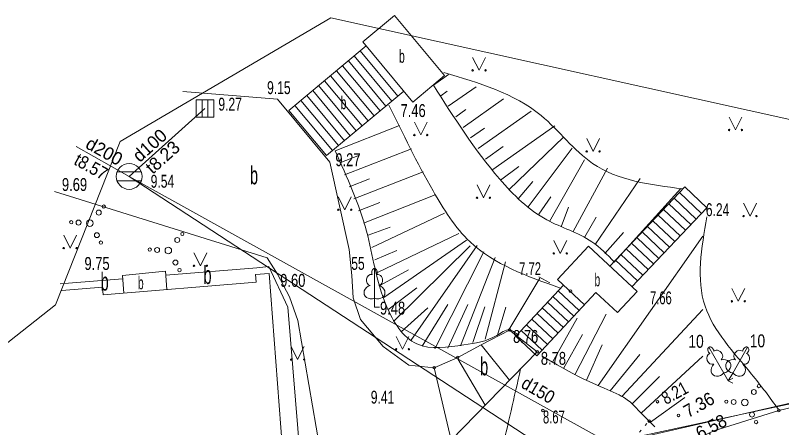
# Model space of a CAD drawing. Extents: x -1325 to -1182, y 698 to 905.
# Drawn here: x -1262.25 to -1232.55, y 829.61 to 845.58 of the extents above; entities that cross this region are included whole.
import ezdxf
from ezdxf.enums import TextEntityAlignment as Align

# ---------------------------------------------------------------- set-up
doc = ezdxf.new("R2010")
doc.units = 0
doc.header["$LTSCALE"] = 0.2
doc.linetypes.add('DOTTED', pattern=[1.5, 0.3, -1.2])
for name, color, linetype, lineweight in [('1', 7, 'Continuous', 13), ('20', 7, 'Continuous', 13), ('28', 7, 'Continuous', 13), ('3', 7, 'Continuous', 13), ('30', 7, 'Continuous', 13), ('5', 7, 'Continuous', 13), ('55', 7, 'Continuous', 13), ('56', 7, 'Continuous', 13), ('57', 7, 'DOTTED', 13), ('59', 7, 'Continuous', 13), ('6', 7, 'Continuous', 13), ('61', 7, 'Continuous', 13), ('62', 7, 'Continuous', 13), ('63', 7, 'Continuous', 13)]:
    doc.layers.add(name, color=color, linetype=linetype, lineweight=lineweight)
for name, color, linetype in [('10', 7, 'Continuous'), ('11', 7, 'Continuous'), ('12', 7, 'Continuous'), ('15', 7, 'Continuous'), ('32', 7, 'Continuous'), ('8', 7, 'Continuous')]:
    doc.layers.add(name, color=color, linetype=linetype)

msp = doc.modelspace()

# ---------------------------------------------------------------- linework, layer by layer
at = {"layer": '1'}
for p, q in [((-1246.042, 842.876), (-1245.457, 843.289)), ((-1245.753, 842.467), (-1245.505, 842.643)), ((-1245.465, 842.059), (-1244.391, 842.818)), ((-1244.888, 841.242), (-1243.325, 842.347)), ((-1245.177, 841.651), (-1244.781, 841.93)), ((-1244.311, 840.425), (-1242.259, 841.875)), ((-1249.854, 840.332), (-1247.357, 841.312)), ((-1244.6, 840.834), (-1244.057, 841.217)), ((-1243.734, 839.609), (-1241.338, 841.301)), ((-1243.123, 838.819), (-1240.994, 840.873)), ((-1244.023, 840.017), (-1243.336, 840.502)), ((-1249.488, 839.401), (-1246.898, 840.418)), ((-1242.368, 838.165), (-1240.663, 840.435)), ((-1249.671, 839.867), (-1248.908, 840.166)), ((-1241.546, 837.596), (-1240.185, 839.985)), ((-1243.445, 839.201), (-1242.727, 839.726)), ((-1240.623, 837.215), (-1239.298, 839.658)), ((-1249.123, 838.47), (-1246.438, 839.524)), ((-1249.305, 838.936), (-1248.514, 839.246)), ((-1242.759, 838.476), (-1242.19, 839.142)), ((-1239.776, 836.7), (-1238.035, 839.268)), ((-1239.035, 836.028), (-1236.448, 838.881)), ((-1248.757, 837.539), (-1245.98, 838.63)), ((-1241.961, 837.875), (-1241.49, 838.556)), ((-1248.94, 838.005), (-1248.12, 838.327)), ((-1241.092, 837.387), (-1240.805, 838.157)), ((-1248.429, 836.596), (-1245.619, 837.924)), ((-1240.169, 837.007), (-1239.737, 837.762)), ((-1248.577, 837.073), (-1247.72, 837.383)), ((-1248.204, 835.622), (-1245.058, 837.128)), ((-1239.653, 831.243), (-1235.601, 837.032)), ((-1239.405, 836.364), (-1238.68, 837.165)), ((-1247.968, 834.65), (-1244.762, 836.878)), ((-1247.588, 833.728), (-1244.621, 836.66)), ((-1246.92, 832.994), (-1244.347, 836.669)), ((-1248.309, 836.11), (-1247.459, 836.473)), ((-1245.987, 832.671), (-1244.091, 836.426)), ((-1244.997, 832.783), (-1243.655, 836.207)), ((-1244.033, 833.046), (-1243.249, 836.036)), ((-1248.095, 835.134), (-1247.007, 835.724)), ((-1243.118, 833.404), (-1241.924, 835.396)), ((-1247.807, 834.177), (-1246.68, 835.022)), ((-1247.294, 833.325), (-1246.261, 834.252)), ((-1246.477, 832.766), (-1245.479, 834.382)), ((-1245.489, 832.691), (-1244.715, 834.382)), ((-1244.513, 832.907), (-1244.045, 834.288)), ((-1243.556, 833.197), (-1243.234, 834.273)), ((-1240.56, 831.663), (-1239.347, 834.009)), ((-1238.745, 830.824), (-1235.601, 834.194)), ((-1241.432, 832.152), (-1240.476, 833.853)), ((-1240.996, 831.907), (-1240.261, 833.214)), ((-1240.109, 831.447), (-1239.498, 832.816)), ((-1239.198, 831.035), (-1238.041, 832.447)), ((-1237.99, 830.176), (-1235.601, 832.375)), ((-1238.343, 830.529), (-1237.283, 831.591)), ((-1237.636, 829.823), (-1236.293, 830.774))]:
    msp.add_line(p, q, dxfattribs=at)
msp.add_lwpolyline([(-1237.459, 829.646), (-1237.914, 830.1), (-1238.369, 830.555), (-1238.424, 830.606), (-1238.478, 830.651), (-1238.53, 830.691), (-1238.581, 830.726), (-1238.679, 830.787), (-1238.769, 830.837), (-1238.849, 830.877), (-1239.425, 831.137), (-1239.58, 831.21), (-1240.128, 831.455), (-1240.264, 831.517), (-1240.466, 831.615), (-1240.565, 831.666), (-1240.664, 831.72), (-1241.247, 832.048), (-1241.829, 832.375)], dxfattribs=at)
for points in [[(-1246.042, 842.876), (-1243.477, 839.245), (-1241.649, 837.661), (-1239.902, 836.815), (-1239.029, 836.023)], [(-1249.854, 840.332), (-1248.633, 837.222), (-1247.863, 834.323), (-1246.685, 832.854), (-1244.862, 832.815), (-1243.584, 833.187), (-1243.096, 833.394), (-1242.798, 833.227)], [(-1235.871, 827.931), (-1235.166, 828.433), (-1231.672, 829.028), (-1224.12, 831.442)]]:
    msp.add_spline(points, degree=3, dxfattribs=at)
at = {"layer": '20'}
msp.add_lwpolyline([(-1251.428, 785.238), (-1264.287, 784.95), (-1270.386, 788.761), (-1278.142, 789.522), (-1278.429, 820.375), (-1260.691, 834.371), (-1258.18, 840.695), (-1250.014, 845.483), (-1229.719, 840.991), (-1227.82, 835.408), (-1218.991, 825.806), (-1239.144, 811.691), (-1246.245, 803.625), (-1250.023, 795.415), (-1251.371, 785.664)], close=True, dxfattribs=at)
at = {"layer": '28'}
for p, q in [((-1255.009, 842.31), (-1255.009, 841.635)), ((-1254.784, 842.31), (-1254.784, 841.635)), ((-1258.301, 839.518), (-1257.365, 839.518)), ((-1258.301, 839.168), (-1257.365, 839.168))]:
    msp.add_line(p, q, dxfattribs=at)
msp.add_lwpolyline([(-1255.234, 842.31), (-1254.559, 842.31), (-1254.559, 841.635), (-1255.234, 841.635)], close=True, dxfattribs=at)
msp.add_circle((-1257.8326, 839.343), 0.5, dxfattribs=at)
at = {"layer": '3'}
for p in [(-1236.491, 827.506), (-1232.369, 822.724)]:
    msp.add_line(p, (-1257.833, 839.343), dxfattribs=at)
msp.add_lwpolyline([(-1254.897, 841.973), (-1257.833, 839.343), (-1259.889, 840.496)], dxfattribs=at)
at = {"layer": '30'}
msp.add_spline([(-1247.278, 818.829), (-1245.467, 822.244), (-1243.42, 828.633), (-1242.662, 831.887)], degree=3, dxfattribs=at)
at = {"layer": '5'}
for p, q in [((-1248.327, 835.778), (-1248.327, 834.625)), ((-1248.237, 835.546), (-1248.238, 835.546)), ((-1248.327, 834.625), (-1248.327, 834.278)), ((-1248.327, 834.278), (-1248.127, 834.278)), ((-1235.366, 832.728), (-1234.789, 831.729)), ((-1235.172, 832.572), (-1235.173, 832.572)), ((-1233.866, 832.728), (-1234.442, 831.729)), ((-1233.904, 832.482), (-1233.905, 832.483)), ((-1234.789, 831.729), (-1234.616, 831.429)), ((-1234.442, 831.729), (-1234.616, 831.429)), ((-1234.616, 831.429), (-1234.442, 831.529)), ((-1234.616, 831.429), (-1234.442, 831.329))]:
    msp.add_line(p, q, dxfattribs=at)
for points in [[(-1244.523, 843.953), (-1244.273, 843.453), (-1244.023, 843.953)], [(-1246.781, 841.448), (-1246.531, 840.948), (-1246.281, 841.448)], [(-1234.585, 841.642), (-1234.335, 841.142), (-1234.085, 841.642)], [(-1240.102, 840.813), (-1239.852, 840.313), (-1239.602, 840.813)], [(-1244.352, 839.018), (-1244.102, 838.518), (-1243.852, 839.018)], [(-1249.728, 838.554), (-1249.478, 838.054), (-1249.228, 838.554)], [(-1234.023, 838.306), (-1233.773, 837.806), (-1233.523, 838.306)], [(-1260.37, 837.066), (-1260.12, 836.566), (-1259.87, 837.066)], [(-1241.378, 836.861), (-1241.128, 836.361), (-1240.878, 836.861)], [(-1255.322, 836.383), (-1255.072, 835.883), (-1254.822, 836.383)], [(-1234.477, 835.007), (-1234.227, 834.507), (-1233.977, 835.007)], [(-1247.49, 833.148), (-1247.24, 832.648), (-1246.99, 833.148)], [(-1251.556, 832.752), (-1251.306, 832.252), (-1251.056, 832.752)]]:
    msp.add_lwpolyline(points, dxfattribs=at)
for centre, radius in [((-1244.5228, 843.4524), 0.028), ((-1244.0228, 843.4524), 0.0263), ((-1234.5849, 841.1416), 0.028), ((-1234.0849, 841.1416), 0.0263), ((-1246.7808, 840.9474), 0.028), ((-1246.2808, 840.9474), 0.0263), ((-1240.1018, 840.3128), 0.028), ((-1239.6018, 840.3128), 0.0263), ((-1244.3522, 838.5175), 0.028), ((-1243.8522, 838.5175), 0.0263), ((-1258.817, 838.1739), 0.064), ((-1259.0134, 837.9422), 0.096), ((-1249.7279, 838.0533), 0.028), ((-1249.2279, 838.0533), 0.0263), ((-1234.0236, 837.806), 0.028), ((-1233.5236, 837.806), 0.0263), ((-1260.0794, 837.5688), 0.064), ((-1259.7949, 837.5554), 0.096), ((-1259.361, 837.5346), 0.128), ((-1259.0845, 837.0677), 0.096), ((-1255.9697, 836.8818), 0.096), ((-1255.7732, 837.1135), 0.064), ((-1258.927, 836.7784), 0.064), ((-1260.3703, 836.5652), 0.028), ((-1259.8703, 836.5652), 0.0263), ((-1257.0356, 836.5084), 0.064), ((-1256.7511, 836.4949), 0.096), ((-1256.3172, 836.4741), 0.128), ((-1241.3779, 836.3605), 0.028), ((-1240.8779, 836.3605), 0.0263), ((-1256.0407, 836.0073), 0.096), ((-1255.8833, 835.718), 0.064), ((-1255.3221, 835.8826), 0.028), ((-1254.8221, 835.8826), 0.0263), ((-1234.4772, 834.507), 0.028), ((-1233.9772, 834.507), 0.0263), ((-1247.4903, 832.6474), 0.028), ((-1246.9903, 832.6474), 0.0263), ((-1251.5564, 832.2513), 0.028), ((-1251.0564, 832.2513), 0.0263), ((-1233.4286, 831.2243), 0.064), ((-1233.6251, 830.9926), 0.096), ((-1234.4065, 830.6058), 0.096), ((-1233.9726, 830.585), 0.128), ((-1234.691, 830.6192), 0.064), ((-1233.6961, 830.1181), 0.096), ((-1233.5387, 829.8288), 0.064)]:
    msp.add_circle(centre, radius, dxfattribs=at)
for centre, major_axis, ratio, start_param, end_param in [((-1248.3262, 835.628), (0, -0.1499), 0.707107, 3.1453698, 5.2874846), ((-1248.327, 835.628), (0, -0.1499), 0.707107, 0.9957007, 3.1378155), ((-1248.4549, 835.3332), (-0.0387, -0.2124), 0.861323, 3.1415927, 6.2831853), ((-1248.1983, 835.3332), (0.0387, -0.2124), 0.861323, 6.2831853, 9.424778), ((-1248.4162, 834.8709), (0.3068, 0.0951), 0.814445, 1.5707963, 4.7520146), ((-1248.237, 834.8709), (-0.3068, 0.0951), 0.814445, 1.5311707, 4.712389), ((-1235.2543, 832.2786), (0.0727, -0.2033), 0.861323, 3.1415927, 6.2831853), ((-1235.2903, 832.5984), (0.075, -0.1298), 0.707107, 3.1453698, 5.2874846), ((-1235.291, 832.5979), (0.075, -0.1298), 0.707107, 0.9957007, 3.1378155), ((-1235.0321, 832.4069), (0.1397, -0.1646), 0.861323, 6.2831853, 9.424778), ((-1234.1991, 832.4069), (-0.1397, -0.1646), 0.861323, 3.1415927, 6.2831853), ((-1233.9402, 832.5979), (-0.075, -0.1298), 0.707107, 3.1453698, 5.2874846), ((-1233.9769, 832.2786), (-0.0727, -0.2033), 0.861323, 6.2831853, 9.424778), ((-1233.9409, 832.5984), (-0.075, -0.1298), 0.707107, 0.9957007, 3.1378155), ((-1234.8345, 831.9872), (-0.3133, -0.071), 0.814445, 1.5311707, 4.712389), ((-1234.3967, 831.9872), (0.3133, -0.071), 0.814445, 1.5707963, 4.7520146), ((-1234.9896, 831.8977), (0.2182, 0.2358), 0.814445, 1.5707963, 4.7520146), ((-1234.2416, 831.8977), (-0.2182, 0.2358), 0.814445, 1.5311707, 4.712389)]:
    msp.add_ellipse(centre, major_axis=major_axis, ratio=ratio, start_param=start_param, end_param=end_param, dxfattribs=at)
at = {"layer": '55'}
msp.add_lwpolyline([(-1279.322, 790.175), (-1264.692, 791.666), (-1263.121, 794.463), (-1263.06, 799.299), (-1247.785, 816.834), (-1237.845, 829.32), (-1225.799, 831.912), (-1223.768, 834.184)], dxfattribs=at)
at = {"layer": '56'}
for p, q in [((-1248.878, 844.204), (-1247.421, 842.455)), ((-1249.339, 843.82), (-1247.882, 842.071)), ((-1249.108, 844.012), (-1247.651, 842.263)), ((-1249.569, 843.628), (-1248.112, 841.879)), ((-1250.03, 843.244), (-1248.573, 841.495)), ((-1249.8, 843.436), (-1248.343, 841.687)), ((-1250.261, 843.052), (-1248.804, 841.303)), ((-1250.722, 842.668), (-1249.265, 840.919)), ((-1250.491, 842.86), (-1249.034, 841.111)), ((-1251.183, 842.284), (-1249.726, 840.535)), ((-1250.952, 842.476), (-1249.495, 840.727)), ((-1251.413, 842.092), (-1249.956, 840.343)), ((-1239.204, 835.872), (-1236.303, 838.935)), ((-1235.659, 837.912), (-1236.509, 838.717)), ((-1235.453, 838.13), (-1236.303, 838.935)), ((-1235.866, 837.694), (-1236.716, 838.499)), ((-1238.348, 835.073), (-1235.453, 838.13)), ((-1236.072, 837.477), (-1236.922, 838.282)), ((-1236.484, 837.041), (-1237.334, 837.846)), ((-1236.278, 837.259), (-1237.128, 838.064)), ((-1236.691, 836.823), (-1237.541, 837.628)), ((-1236.897, 836.605), (-1237.747, 837.41)), ((-1237.31, 836.17), (-1238.16, 836.975)), ((-1237.103, 836.387), (-1237.953, 837.192)), ((-1241.237, 835.352), (-1240.03, 836.644)), ((-1240.03, 836.644), (-1238.152, 834.89)), ((-1237.516, 835.952), (-1238.366, 836.757)), ((-1237.722, 835.734), (-1238.572, 836.539)), ((-1238.135, 835.298), (-1238.985, 836.103)), ((-1237.928, 835.516), (-1238.778, 836.321)), ((-1241.237, 835.352), (-1240.189, 834.373)), ((-1241.004, 835.134), (-1242.847, 833.161)), ((-1242.032, 832.4), (-1239.746, 834.847)), ((-1241.209, 834.915), (-1240.394, 834.154)), ((-1238.915, 834.072), (-1239.746, 834.847)), ((-1238.915, 834.072), (-1238.152, 834.89)), ((-1241.414, 834.696), (-1240.599, 833.935)), ((-1241.823, 834.257), (-1241.008, 833.496)), ((-1241.619, 834.477), (-1240.804, 833.716)), ((-1242.028, 834.038), (-1241.213, 833.277)), ((-1242.233, 833.819), (-1241.418, 833.058)), ((-1242.642, 833.38), (-1241.827, 832.619)), ((-1242.438, 833.6), (-1241.623, 832.839)), ((-1242.847, 833.161), (-1242.032, 832.4))]:
    msp.add_line(p, q, dxfattribs=at)
msp.add_lwpolyline([(-1247.556, 845.583), (-1248.784, 844.56), (-1246.839, 842.225), (-1245.611, 843.247)], close=True, dxfattribs=at)
for points in [[(-1248.648, 844.396), (-1251.644, 841.9), (-1250.187, 840.151), (-1247.191, 842.647)], [(-1258.042, 834.827), (-1258.097, 835.506), (-1256.426, 835.672), (-1256.368, 834.963)]]:
    msp.add_lwpolyline(points, dxfattribs=at)
at = {"layer": '57'}
msp.add_line((-1246.776, 819.001), (-1237.687, 829.874), dxfattribs=at)
at = {"layer": '59'}
msp.add_lwpolyline([(-1251.821, 827.92), (-1252.404, 835.587), (-1252.932, 835.538), (-1252.908, 835.245), (-1258.847, 834.761), (-1258.871, 835.05), (-1260.438, 834.929)], dxfattribs=at)
at = {"layer": '6'}
for centre in [(-1240.7326, 834.897), (-1243.0956, 833.394), (-1242.0196, 832.546), (-1245.1026, 832.332), (-1246.0116, 831.935), (-1237.3632, 830.6163), (-1241.7986, 830.275), (-1236.5433, 830.0862), (-1232.6546, 830.279), (-1237.6776, 829.868)]:
    msp.add_circle(centre, 0.05, dxfattribs=at)
at = {"layer": '61'}
msp.add_lwpolyline([(-1249.819, 814.203), (-1246.581, 818.124), (-1237.968, 829.25), (-1225.679, 832.058)], dxfattribs=at)
at = {"layer": '62'}
msp.add_line((-1241.959, 835.451), (-1241.537, 835.228), dxfattribs=at)
for points in [[(-1245.633, 843.367), (-1241.867, 841.702), (-1239.875, 839.845), (-1236.382, 838.862)], [(-1241.123, 835.019), (-1244.624, 836.811), (-1246.059, 838.788), (-1247.766, 842.107)], [(-1235.444, 837.774), (-1235.516, 834.318), (-1233.714, 831.689), (-1232.669, 830.321)]]:
    msp.add_spline(points, degree=3, dxfattribs=at)
at = {"layer": '63'}
for p, q in [((-1260.506, 835.185), (-1258.087, 835.382)), ((-1244.191, 832.814), (-1243.088, 831.451)), ((-1245.103, 832.279), (-1244.037, 830.479)), ((-1245.357, 829.125), (-1246.012, 831.935))]:
    msp.add_line(p, q, dxfattribs=at)
for points in [[(-1243.096, 833.394), (-1244.191, 832.814), (-1245.103, 832.332), (-1246.012, 831.935), (-1246.99, 832.03), (-1247.991, 832.758), (-1248.872, 833.799), (-1249.154, 834.641), (-1249.207, 835.507), (-1249.314, 836.514), (-1250.061, 839.893), (-1252.08, 842.338), (-1255.757, 842.638)], [(-1250.446, 828.799), (-1251.292, 833.762), (-1251.62, 834.676), (-1252.091, 835.555), (-1252.492, 836.196), (-1260.722, 838.754)], [(-1256.413, 835.518), (-1252.89, 835.805), (-1252.421, 835.858), (-1251.683, 834.285), (-1251.194, 828.321)], [(-1256.412, 818.123), (-1256.201, 815.29), (-1252.408, 813.098), (-1251.504, 813.774), (-1247.278, 818.829), (-1247.088, 823.447), (-1246.858, 826.564), (-1246.095, 828.381), (-1245.357, 829.125), (-1242.02, 832.546), (-1243.096, 833.394)], [(-1225.119, 832.074), (-1232.655, 830.279), (-1235.176, 829.494), (-1238.254, 828.059), (-1240.45, 824.627), (-1244.966, 819.561)]]:
    msp.add_lwpolyline(points, dxfattribs=at)

# ---------------------------------------------------------------- texts
at = {"layer": '10', "width": 0.6}
for p in [(-1252.9955, 839.037), (-1254.7975, 835.175), (-1258.7855, 834.922), (-1244.0765, 831.637)]:
    msp.add_text('b', height=0.7, dxfattribs=at).set_placement(p, align=Align.CENTER)
at = {"layer": '11'}
for s, rotation, p in [('d100', 41.853, (-1256.8713, 840.3593)), ('d200', 330.715, (-1258.9198, 840.1022)), ('t8.23', 41.853, (-1256.3723, 839.901))]:
    msp.add_text(s, height=0.5, rotation=rotation, dxfattribs=at).set_placement(p, align=Align.CENTER)
at = {"layer": '11', "width": 0.9}
for s, rotation, p in [('t8.57', 330.715, (-1259.4308, 839.5063)), ('d150', 329.713, (-1242.1071, 830.8545))]:
    msp.add_text(s, height=0.5, rotation=rotation, dxfattribs=at).set_placement(p, align=Align.CENTER)
at = {"layer": '12'}
for s, width, p in [('55', 0.7, (-1249.228, 835.725)), ('10    ', 0.8, (-1236.162, 832.706)), ('10    ', 0.8, (-1233.782, 832.724))]:
    msp.add_text(s, height=0.5, dxfattribs=dict(at, width=width)).set_placement(p)
at = {"layer": '15', "width": 0.6}
for p in [(-1247.377, 843.746), (-1249.64, 841.945), (-1257.496, 834.971), (-1239.801, 835.088)]:
    msp.add_text('b', height=0.5, dxfattribs=at).set_placement(p)
at = {"layer": '32', "width": 0.7}
for s, p in [('9.27', (-1254.377, 841.893)), ('9.54', (-1257, 838.905))]:
    msp.add_text(s, height=0.5, dxfattribs=at).set_placement(p)
at = {"layer": '8'}
for s, width, p in [(' 9.15', 0.7, (-1252.619, 842.532)), (' 7.46', 0.75, (-1247.457, 841.644)), (' 9.27', 0.75, (-1249.983, 839.74)), (' 9.69', 0.75, (-1260.579, 838.779)), ('6.24', 0.7, (-1235.486, 837.804)), (' 9.75', 0.75, (-1259.706, 835.721)), ('7.72', 0.65, (-1242.72, 835.52)), (' 9.60', 0.75, (-1252.12, 835.066)), ('7.66', 0.65, (-1237.652, 834.39)), (' 9.48', 0.75, (-1248.253, 833.991)), (' 8.76', 0.75, (-1243.096, 832.894)), (' 8.78', 0.75, (-1242.02, 832.046)), (' 9.41', 0.7, (-1248.6, 830.544)), ('8.67', 0.65, (-1241.798, 829.775))]:
    msp.add_text(s, height=0.5, dxfattribs=dict(at, width=width)).set_placement(p)
for s, rotation, width, p in [('8.21', 28.445, 0.8, (-1237.034, 830.489)), (' 7.36', 29.366, 0.95, (-1236.325, 829.891)), (' 6.58', 28.573, 0.95, (-1235.857, 829.05))]:
    msp.add_text(s, height=0.5, rotation=rotation, dxfattribs=dict(at, width=width)).set_placement(p)

doc.saveas('drawing.dxf')
